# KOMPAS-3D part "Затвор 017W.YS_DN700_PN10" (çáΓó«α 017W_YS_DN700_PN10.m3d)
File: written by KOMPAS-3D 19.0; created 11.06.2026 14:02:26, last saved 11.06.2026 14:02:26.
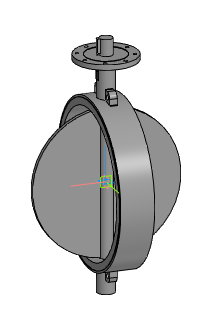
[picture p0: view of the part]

Document properties: Автор: Евгений; Полное имя файла: Z:\3.Личные\kachalov\001_3d для проектировщиков\x.x Тип 017W.Y(S) Затвор дисковый поворотный межфланцевый\_stp_Затвор 017W.YS_DN32-DN1200\Затвор 017W_YS_DN700_PN10.m3d

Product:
- Part/product: Затвор 017W.YS_DN700_PN10

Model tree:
1. Операция без истории:1  (labels: Затвор 017W.YS_DN700_PN10)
